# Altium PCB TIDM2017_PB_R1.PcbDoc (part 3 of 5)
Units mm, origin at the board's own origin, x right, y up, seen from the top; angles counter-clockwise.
Board outline 120 x 147.5 mm, 4 copper layers (Top Layer, L2, L3, Bottom Layer), stack 1.413 mm thick; 117 components, 53 nets, 3137 pads, 96 vias.
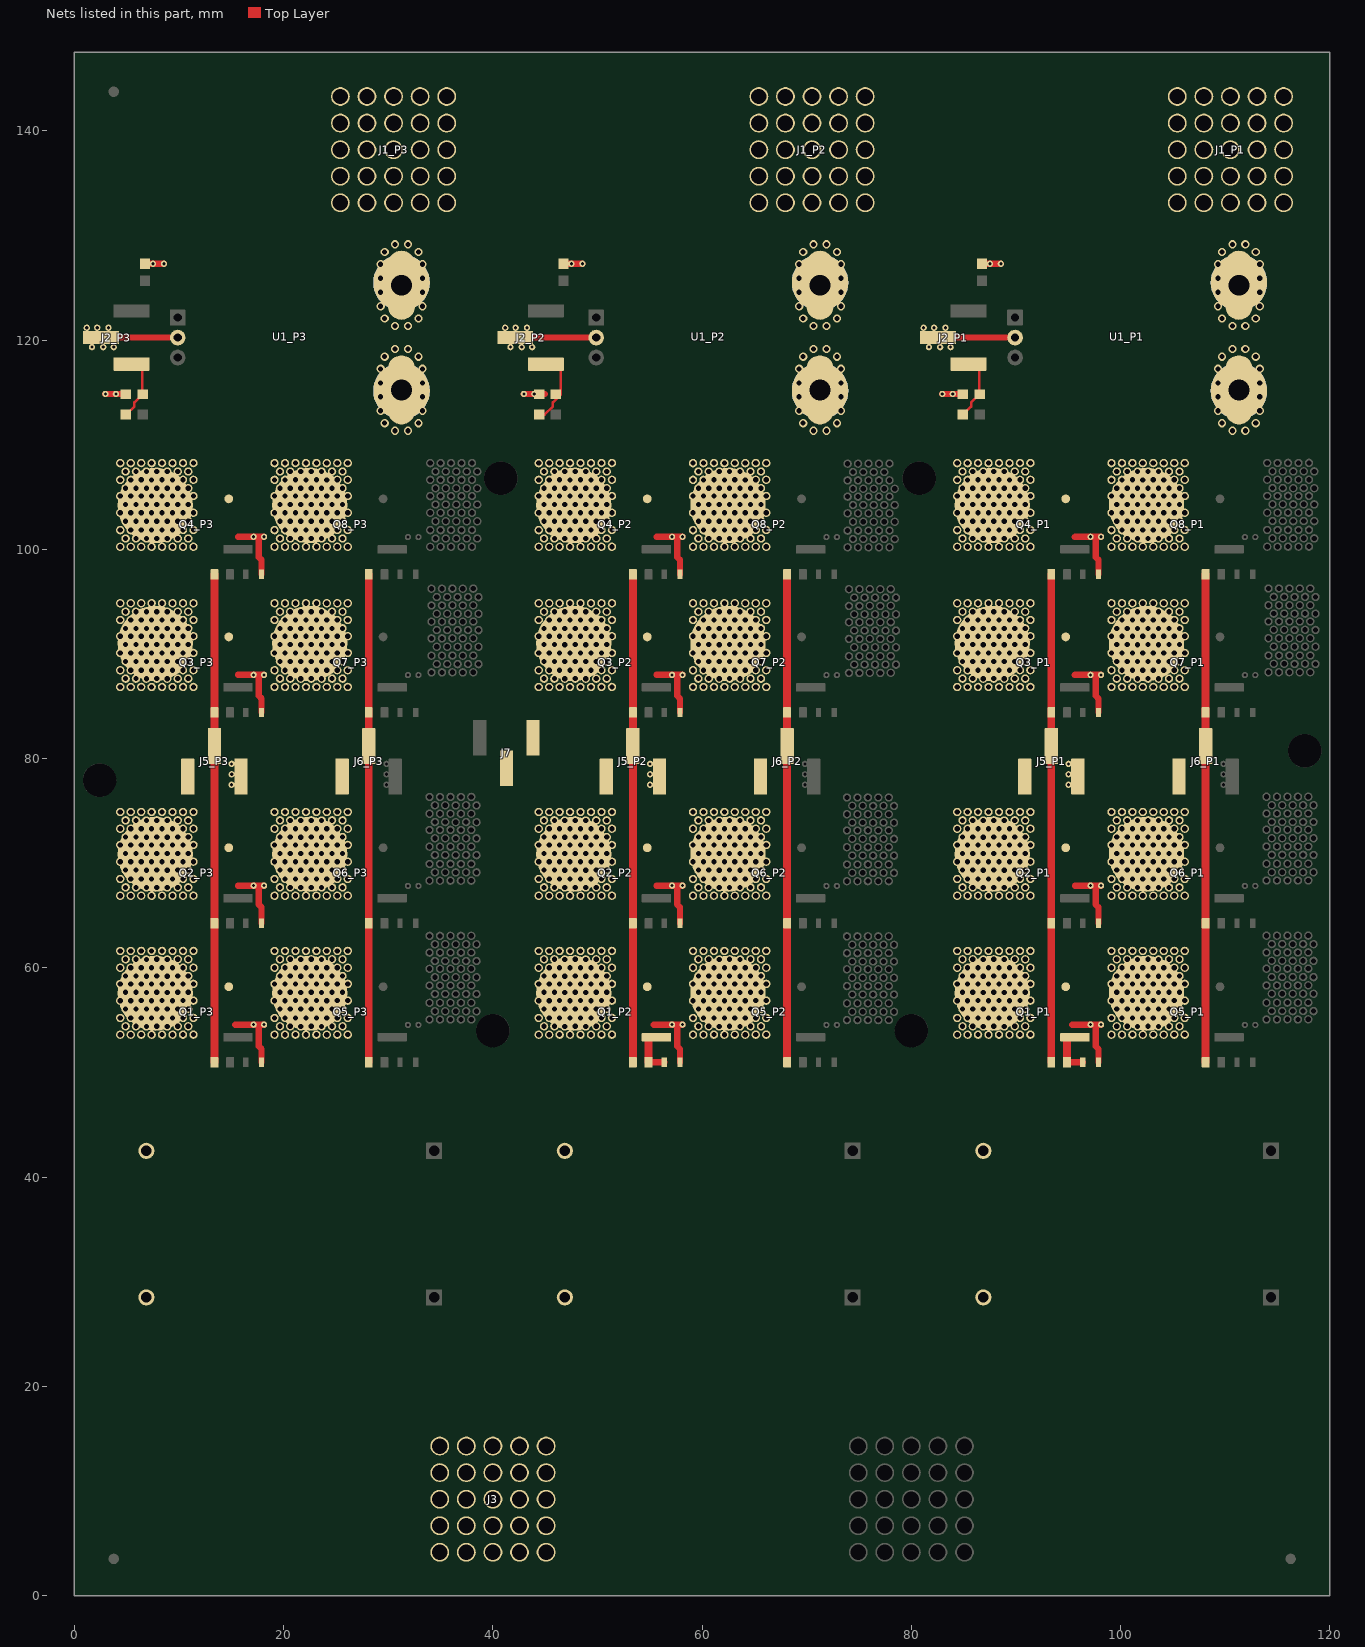
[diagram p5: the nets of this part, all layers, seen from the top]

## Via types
v1: diameter 0.8, hole 0.5, Top Layer to Bottom Layer, 96 vias

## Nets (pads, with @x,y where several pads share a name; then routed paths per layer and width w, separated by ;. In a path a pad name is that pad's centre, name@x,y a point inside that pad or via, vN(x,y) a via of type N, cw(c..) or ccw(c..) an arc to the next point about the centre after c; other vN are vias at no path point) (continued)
D_HS_P1: C1_P1.2 C1_P2.2 C1_P3.2 C2_P1.2 C2_P2.2 C2_P3.2 J3.1 J5_P1.3 J5_P2.3 J5_P3.3 J7.2 J7.3 pad.2@4.376,53.611 pad.2@4.376,55.211 pad.2@4.376,56.861 pad.2@4.376,58.461 pad.2@4.376,60.014 pad.2@4.376,61.614 pad.2@4.376,66.894 pad.2@4.376,68.494 pad.2@4.376,70.144 pad.2@4.376,71.744 pad.2@4.376,73.297 pad.2@4.376,74.897 pad.2@4.376,86.847 pad.2@4.376,88.447 pad.2@4.376,90.097 pad.2@4.376,91.697 pad.2@4.376,93.25 pad.2@4.376,94.85 pad.2@4.376,100.242 pad.2@4.376,101.842 pad.2@4.376,103.492 pad.2@4.376,105.092 pad.2@4.376,106.644 pad.2@4.376,108.244 pad.2@4.889,54.409 pad.2@4.889,56.059 pad.2@4.889,57.659 pad.2@4.889,59.212 pad.2@4.889,60.812 pad.2@4.889,67.693 pad.2@4.889,69.343 pad.2@4.889,70.943 pad.2@4.889,72.496 pad.2@4.889,74.096 pad.2@4.889,87.646 pad.2@4.889,89.296 pad.2@4.889,90.896 pad.2@4.889,92.448 pad.2@4.889,94.048 pad.2@4.889,101.04 pad.2@4.889,102.69 pad.2@4.889,104.29 pad.2@4.889,105.843 pad.2@4.889,107.443 pad.2@5.376,53.611 pad.2@5.376,55.211 pad.2@5.376,56.861 pad.2@5.376,58.461 pad.2@5.376,60.014 pad.2@5.376,61.614 pad.2@5.376,66.894 pad.2@5.376,68.494 pad.2@5.376,70.144 pad.2@5.376,71.744 pad.2@5.376,73.297 pad.2@5.376,74.897 pad.2@5.376,86.847 pad.2@5.376,88.447 pad.2@5.376,90.097 pad.2@5.376,91.697 pad.2@5.376,93.25 pad.2@5.376,94.85 pad.2@5.376,100.242 pad.2@5.376,101.842 pad.2@5.376,103.492 pad.2@5.376,105.092 pad.2@5.376,106.644 pad.2@5.376,108.244 pad.2@5.876,54.409 pad.2@5.876,56.059 pad.2@5.876,57.659 pad.2@5.876,59.212 pad.2@5.876,60.812 pad.2@5.876,67.693 pad.2@5.876,69.343 pad.2@5.876,70.943 pad.2@5.876,72.496 pad.2@5.876,74.096 pad.2@5.876,87.646 pad.2@5.876,89.296 pad.2@5.876,90.896 pad.2@5.876,92.448 pad.2@5.876,94.048 pad.2@5.876,101.04 pad.2@5.876,102.69 pad.2@5.876,104.29 pad.2@5.876,105.843 pad.2@5.876,107.443 pad.2@6.376,53.616 pad.2@6.376,55.216 pad.2@6.376,56.866 pad.2@6.376,58.466 pad.2@6.376,60.019 pad.2@6.376,61.619 pad.2@6.376,66.9 pad.2@6.376,68.5 pad.2@6.376,70.15 pad.2@6.376,71.75 pad.2@6.376,73.303 pad.2@6.376,74.903 pad.2@6.376,86.853 pad.2@6.376,88.453 pad.2@6.376,90.103 pad.2@6.376,91.703 pad.2@6.376,93.256 pad.2@6.376,94.855 pad.2@6.376,100.247 pad.2@6.376,101.847 pad.2@6.376,103.497 pad.2@6.376,105.097 pad.2@6.376,106.65 pad.2@6.376,108.25 pad.2@6.876,54.404 pad.2@6.876,56.054 pad.2@6.876,57.654 pad.2@6.876,59.207 pad.2@6.876,60.807 pad.2@6.876,67.687 pad.2@6.876,69.337 pad.2@6.876,70.937 pad.2@6.876,72.49 pad.2@6.876,74.09 pad.2@6.876,87.64 pad.2@6.876,89.29 pad.2@6.876,90.89 pad.2@6.876,92.443 pad.2@6.876,94.043 pad.2@6.876,101.035 pad.2@6.876,102.685 pad.2@6.876,104.285 pad.2@6.876,105.837 pad.2@6.876,107.437 pad.2@7.376,53.611 pad.2@7.376,55.211 pad.2@7.376,56.861 pad.2@7.376,58.461 pad.2@7.376,60.014 pad.2@7.376,61.614 pad.2@7.376,66.894 pad.2@7.376,68.494 pad.2@7.376,70.144 pad.2@7.376,71.744 pad.2@7.376,73.297 pad.2@7.376,74.897 pad.2@7.376,86.847 pad.2@7.376,88.447 pad.2@7.376,90.097 pad.2@7.376,91.697 pad.2@7.376,93.25 pad.2@7.376,94.85 pad.2@7.376,100.242 pad.2@7.376,101.842 pad.2@7.376,103.492 pad.2@7.376,105.092 pad.2@7.376,106.644 pad.2@7.376,108.244 pad.2@7.876,54.409 pad.2@7.876,56.059 pad.2@7.876,57.659 pad.2@7.876,59.212 pad.2@7.876,60.812 pad.2@7.876,67.693 pad.2@7.876,69.343 pad.2@7.876,70.943 pad.2@7.876,72.496 pad.2@7.876,74.096 pad.2@7.876,87.646 pad.2@7.876,89.296 pad.2@7.876,90.896 pad.2@7.876,92.448 pad.2@7.876,94.048 pad.2@7.876,101.04 pad.2@7.876,102.69 pad.2@7.876,104.29 pad.2@7.876,105.843 pad.2@7.876,107.443 pad.2@8.376,53.616 pad.2@8.376,55.216 pad.2@8.376,56.866 pad.2@8.376,58.466 pad.2@8.376,60.019 pad.2@8.376,61.619 pad.2@8.376,66.9 pad.2@8.376,68.5 pad.2@8.376,70.15 pad.2@8.376,71.75 pad.2@8.376,73.303 pad.2@8.376,74.903 pad.2@8.376,86.853 pad.2@8.376,88.453 pad.2@8.376,90.103 pad.2@8.376,91.703 pad.2@8.376,93.256 pad.2@8.376,94.855 pad.2@8.376,100.247 pad.2@8.376,101.847 pad.2@8.376,103.497 pad.2@8.376,105.097 pad.2@8.376,106.65 pad.2@8.376,108.25 pad.2@8.876,54.404 pad.2@8.876,56.054 pad.2@8.876,57.654 pad.2@8.876,59.207 pad.2@8.876,60.807 pad.2@8.876,67.687 pad.2@8.876,69.337 pad.2@8.876,70.937 pad.2@8.876,72.49 pad.2@8.876,74.09 pad.2@8.876,87.64 pad.2@8.876,89.29 pad.2@8.876,90.89 pad.2@8.876,92.443 pad.2@8.876,94.043 pad.2@8.876,101.035 pad.2@8.876,102.685 pad.2@8.876,104.285 pad.2@8.876,105.837 pad.2@8.876,107.437 pad.2@9.376,53.611 pad.2@9.376,55.211 pad.2@9.376,56.861 pad.2@9.376,58.461 pad.2@9.376,60.014 pad.2@9.376,61.614 pad.2@9.376,66.894 pad.2@9.376,68.494 pad.2@9.376,70.144 pad.2@9.376,71.744 pad.2@9.376,73.297 pad.2@9.376,74.897 pad.2@9.376,86.847 pad.2@9.376,88.447 pad.2@9.376,90.097 pad.2@9.376,91.697 pad.2@9.376,93.25 pad.2@9.376,94.85 pad.2@9.376,100.242 pad.2@9.376,101.842 pad.2@9.376,103.492 pad.2@9.376,105.092 pad.2@9.376,106.644 pad.2@9.376,108.244 pad.2@9.876,54.409 pad.2@9.876,56.059 pad.2@9.876,57.659 pad.2@9.876,59.212 pad.2@9.876,60.812 pad.2@9.876,67.693 pad.2@9.876,69.343 pad.2@9.876,70.943 pad.2@9.876,72.496 pad.2@9.876,74.096 pad.2@9.876,87.646 pad.2@9.876,89.296 pad.2@9.876,90.896 pad.2@9.876,92.448 pad.2@9.876,94.048 pad.2@9.876,101.04 pad.2@9.876,102.69 pad.2@9.876,104.29 pad.2@9.876,105.843 pad.2@9.876,107.443 pad.2@10.376,53.616 pad.2@10.376,55.216 pad.2@10.376,56.866 pad.2@10.376,58.466 pad.2@10.376,60.019 pad.2@10.376,61.619 pad.2@10.376,66.9 pad.2@10.376,68.5 pad.2@10.376,70.15 pad.2@10.376,71.75 pad.2@10.376,73.303 pad.2@10.376,74.903 pad.2@10.376,86.853 pad.2@10.376,88.453 pad.2@10.376,90.103 pad.2@10.376,91.703 pad.2@10.376,93.256 pad.2@10.376,94.855 pad.2@10.376,100.247 pad.2@10.376,101.847 pad.2@10.376,103.497 pad.2@10.376,105.097 pad.2@10.376,106.65 pad.2@10.376,108.25 pad.2@10.876,54.409 pad.2@10.876,56.059 pad.2@10.876,57.659 pad.2@10.876,59.212 pad.2@10.876,60.812 pad.2@10.876,67.693 pad.2@10.876,69.343 pad.2@10.876,70.943 pad.2@10.876,72.496 pad.2@10.876,74.096 pad.2@10.876,87.646 pad.2@10.876,89.296 pad.2@10.876,90.896 pad.2@10.876,92.448 pad.2@10.876,94.048 pad.2@10.876,101.04 pad.2@10.876,102.69 pad.2@10.876,104.29 pad.2@10.876,105.843 pad.2@10.876,107.443 pad.2@11.376,53.616 pad.2@11.376,55.216 pad.2@11.376,56.866 pad.2@11.376,58.466 pad.2@11.376,60.019 pad.2@11.376,61.619 pad.2@11.376,66.9 pad.2@11.376,68.5 pad.2@11.376,70.15 pad.2@11.376,71.75 pad.2@11.376,73.303 pad.2@11.376,74.903 pad.2@11.376,86.853 pad.2@11.376,88.453 pad.2@11.376,90.103 pad.2@11.376,91.703 pad.2@11.376,93.256 pad.2@11.376,94.855 pad.2@11.376,100.247 pad.2@11.376,101.847 pad.2@11.376,103.497 pad.2@11.376,105.097 pad.2@11.376,106.65 pad.2@11.376,108.25 pad.2@44.376,53.611 pad.2@44.376,55.211 pad.2@44.376,56.861 pad.2@44.376,58.461 pad.2@44.376,60.014 pad.2@44.376,61.614 pad.2@44.376,66.894 pad.2@44.376,68.494 pad.2@44.376,70.144 pad.2@44.376,71.744 pad.2@44.376,73.297 pad.2@44.376,74.897 pad.2@44.376,86.847 pad.2@44.376,88.447 pad.2@44.376,90.097 pad.2@44.376,91.697 pad.2@44.376,93.25 pad.2@44.376,94.85 pad.2@44.376,100.242 pad.2@44.376,101.842 pad.2@44.376,103.492 pad.2@44.376,105.092 pad.2@44.376,106.644 pad.2@44.376,108.244 pad.2@44.889,54.409 pad.2@44.889,56.059 pad.2@44.889,57.659 pad.2@44.889,59.212 pad.2@44.889,60.812 pad.2@44.889,67.693 pad.2@44.889,69.343 pad.2@44.889,70.943 pad.2@44.889,72.496 pad.2@44.889,74.096 pad.2@44.889,87.646 pad.2@44.889,89.296 pad.2@44.889,90.896 pad.2@44.889,92.448 pad.2@44.889,94.048 pad.2@44.889,101.04 pad.2@44.889,102.69 pad.2@44.889,104.29 pad.2@44.889,105.843 pad.2@44.889,107.443 pad.2@45.376,53.611 pad.2@45.376,55.211 pad.2@45.376,56.861 pad.2@45.376,58.461 pad.2@45.376,60.014 pad.2@45.376,61.614 pad.2@45.376,66.894 pad.2@45.376,68.494 pad.2@45.376,70.144 pad.2@45.376,71.744 pad.2@45.376,73.297 pad.2@45.376,74.897 pad.2@45.376,86.847 pad.2@45.376,88.447 pad.2@45.376,90.097 pad.2@45.376,91.697 pad.2@45.376,93.25 pad.2@45.376,94.85 pad.2@45.376,100.242 pad.2@45.376,101.842 pad.2@45.376,103.492 pad.2@45.376,105.092 pad.2@45.376,106.644 pad.2@45.376,108.244 pad.2@45.876,54.409 pad.2@45.876,56.059 pad.2@45.876,57.659 pad.2@45.876,59.212 pad.2@45.876,60.812 pad.2@45.876,67.693 pad.2@45.876,69.343 pad.2@45.876,70.943 pad.2@45.876,72.496 pad.2@45.876,74.096 pad.2@45.876,87.646 pad.2@45.876,89.296 pad.2@45.876,90.896 pad.2@45.876,92.448 pad.2@45.876,94.048 pad.2@45.876,101.04 pad.2@45.876,102.69 pad.2@45.876,104.29 pad.2@45.876,105.843 pad.2@45.876,107.443 pad.2@46.376,53.616 pad.2@46.376,55.216 pad.2@46.376,56.866 pad.2@46.376,58.466 pad.2@46.376,60.019 pad.2@46.376,61.619 pad.2@46.376,66.9 pad.2@46.376,68.5 pad.2@46.376,70.15 pad.2@46.376,71.75 pad.2@46.376,73.303 pad.2@46.376,74.903 pad.2@46.376,86.853 pad.2@46.376,88.453 pad.2@46.376,90.103 pad.2@46.376,91.703 pad.2@46.376,93.256 pad.2@46.376,94.855 pad.2@46.376,100.247 pad.2@46.376,101.847 pad.2@46.376,103.497 pad.2@46.376,105.097 pad.2@46.376,106.65 pad.2@46.376,108.25 pad.2@46.876,54.404 pad.2@46.876,56.054 pad.2@46.876,57.654 pad.2@46.876,59.207 pad.2@46.876,60.807 pad.2@46.876,67.687 pad.2@46.876,69.337 pad.2@46.876,70.937 pad.2@46.876,72.49 pad.2@46.876,74.09 pad.2@46.876,87.64 pad.2@46.876,89.29 pad.2@46.876,90.89 pad.2@46.876,92.443 pad.2@46.876,94.043 pad.2@46.876,101.035 pad.2@46.876,102.685 pad.2@46.876,104.285 pad.2@46.876,105.837 pad.2@46.876,107.437 pad.2@47.376,53.611 pad.2@47.376,55.211 pad.2@47.376,56.861 pad.2@47.376,58.461 pad.2@47.376,60.014 pad.2@47.376,61.614 pad.2@47.376,66.894 pad.2@47.376,68.494 pad.2@47.376,70.144 pad.2@47.376,71.744 pad.2@47.376,73.297 pad.2@47.376,74.897 pad.2@47.376,86.847 pad.2@47.376,88.447 pad.2@47.376,90.097 pad.2@47.376,91.697 pad.2@47.376,93.25 pad.2@47.376,94.85 pad.2@47.376,100.242 pad.2@47.376,101.842 pad.2@47.376,103.492 pad.2@47.376,105.092 pad.2@47.376,106.644 pad.2@47.376,108.244 pad.2@47.876,54.409 pad.2@47.876,56.059 pad.2@47.876,57.659 pad.2@47.876,59.212 pad.2@47.876,60.812 pad.2@47.876,67.693 pad.2@47.876,69.343 pad.2@47.876,70.943 pad.2@47.876,72.496 pad.2@47.876,74.096 pad.2@47.876,87.646 pad.2@47.876,89.296 pad.2@47.876,90.896 pad.2@47.876,92.448 pad.2@47.876,94.048 pad.2@47.876,101.04 pad.2@47.876,102.69 pad.2@47.876,104.29 pad.2@47.876,105.843 pad.2@47.876,107.443 pad.2@48.376,53.616 pad.2@48.376,55.216 pad.2@48.376,56.866 pad.2@48.376,58.466 pad.2@48.376,60.019 pad.2@48.376,61.619 pad.2@48.376,66.9 pad.2@48.376,68.5 pad.2@48.376,70.15 pad.2@48.376,71.75 pad.2@48.376,73.303 pad.2@48.376,74.903 pad.2@48.376,86.853 pad.2@48.376,88.453 pad.2@48.376,90.103 pad.2@48.376,91.703 pad.2@48.376,93.256 pad.2@48.376,94.855 pad.2@48.376,100.247 pad.2@48.376,101.847 pad.2@48.376,103.497 pad.2@48.376,105.097 pad.2@48.376,106.65 pad.2@48.376,108.25 pad.2@48.876,54.404 pad.2@48.876,56.054 pad.2@48.876,57.654 pad.2@48.876,59.207 pad.2@48.876,60.807 pad.2@48.876,67.687 pad.2@48.876,69.337 pad.2@48.876,70.937 pad.2@48.876,72.49 pad.2@48.876,74.09 pad.2@48.876,87.64 pad.2@48.876,89.29 pad.2@48.876,90.89 pad.2@48.876,92.443 pad.2@48.876,94.043 pad.2@48.876,101.035 pad.2@48.876,102.685 pad.2@48.876,104.285 pad.2@48.876,105.837 pad.2@48.876,107.437 pad.2@49.376,53.611 pad.2@49.376,55.211 pad.2@49.376,56.861 pad.2@49.376,58.461 pad.2@49.376,60.014 pad.2@49.376,61.614 pad.2@49.376,66.894 pad.2@49.376,68.494 pad.2@49.376,70.144 pad.2@49.376,71.744 pad.2@49.376,73.297 pad.2@49.376,74.897 pad.2@49.376,86.847 pad.2@49.376,88.447 pad.2@49.376,90.097 pad.2@49.376,91.697 pad.2@49.376,93.25 pad.2@49.376,94.85 pad.2@49.376,100.242 pad.2@49.376,101.842 pad.2@49.376,103.492 pad.2@49.376,105.092 pad.2@49.376,106.644 pad.2@49.376,108.244 pad.2@49.876,54.409 pad.2@49.876,56.059 pad.2@49.876,57.659 pad.2@49.876,59.212 pad.2@49.876,60.812 pad.2@49.876,67.693 pad.2@49.876,69.343 pad.2@49.876,70.943 pad.2@49.876,72.496 pad.2@49.876,74.096 pad.2@49.876,87.646 pad.2@49.876,89.296 pad.2@49.876,90.896 pad.2@49.876,92.448 pad.2@49.876,94.048 pad.2@49.876,101.04 pad.2@49.876,102.69 pad.2@49.876,104.29 pad.2@49.876,105.843 pad.2@49.876,107.443 pad.2@50.376,53.616 pad.2@50.376,55.216 pad.2@50.376,56.866 pad.2@50.376,58.466 pad.2@50.376,60.019 pad.2@50.376,61.619 pad.2@50.376,66.9 pad.2@50.376,68.5 pad.2@50.376,70.15 pad.2@50.376,71.75 pad.2@50.376,73.303 pad.2@50.376,74.903 pad.2@50.376,86.853 pad.2@50.376,88.453 pad.2@50.376,90.103 pad.2@50.376,91.703 pad.2@50.376,93.256 pad.2@50.376,94.855 pad.2@50.376,100.247 pad.2@50.376,101.847 pad.2@50.376,103.497 pad.2@50.376,105.097 pad.2@50.376,106.65 pad.2@50.376,108.25 pad.2@50.876,54.409 pad.2@50.876,56.059 pad.2@50.876,57.659 pad.2@50.876,59.212 pad.2@50.876,60.812 pad.2@50.876,67.693 pad.2@50.876,69.343 pad.2@50.876,70.943 pad.2@50.876,72.496 pad.2@50.876,74.096 pad.2@50.876,87.646 pad.2@50.876,89.296 pad.2@50.876,90.896 pad.2@50.876,92.448 pad.2@50.876,94.048 pad.2@50.876,101.04 pad.2@50.876,102.69 pad.2@50.876,104.29 pad.2@50.876,105.843 pad.2@50.876,107.443 pad.2@51.376,53.616 pad.2@51.376,55.216 pad.2@51.376,56.866 pad.2@51.376,58.466 pad.2@51.376,60.019 pad.2@51.376,61.619 pad.2@51.376,66.9 pad.2@51.376,68.5 pad.2@51.376,70.15 pad.2@51.376,71.75 pad.2@51.376,73.303 pad.2@51.376,74.903 pad.2@51.376,86.853 pad.2@51.376,88.453 pad.2@51.376,90.103 pad.2@51.376,91.703 pad.2@51.376,93.256 pad.2@51.376,94.855 pad.2@51.376,100.247 pad.2@51.376,101.847 pad.2@51.376,103.497 pad.2@51.376,105.097 pad.2@51.376,106.65 pad.2@51.376,108.25 pad.2@84.376,53.611 pad.2@84.376,55.211 pad.2@84.376,56.861 pad.2@84.376,58.461 pad.2@84.376,60.014 pad.2@84.376,61.614 pad.2@84.376,66.894 pad.2@84.376,68.494 pad.2@84.376,70.144 pad.2@84.376,71.744 pad.2@84.376,73.297 pad.2@84.376,74.897 pad.2@84.376,86.847 pad.2@84.376,88.447 pad.2@84.376,90.097 pad.2@84.376,91.697 pad.2@84.376,93.25 pad.2@84.376,94.85 pad.2@84.376,100.242 pad.2@84.376,101.842 pad.2@84.376,103.492 pad.2@84.376,105.092 pad.2@84.376,106.644 pad.2@84.376,108.244 pad.2@84.889,54.409 pad.2@84.889,56.059 pad.2@84.889,57.659 pad.2@84.889,59.212 pad.2@84.889,60.812 pad.2@84.889,67.693 pad.2@84.889,69.343 pad.2@84.889,70.943 pad.2@84.889,72.496 pad.2@84.889,74.096 pad.2@84.889,87.646 pad.2@84.889,89.296 pad.2@84.889,90.896 pad.2@84.889,92.448 pad.2@84.889,94.048 pad.2@84.889,101.04 pad.2@84.889,102.69 pad.2@84.889,104.29 pad.2@84.889,105.843 pad.2@84.889,107.443 pad.2@85.376,53.611 pad.2@85.376,55.211 pad.2@85.376,56.861 pad.2@85.376,58.461 pad.2@85.376,60.014 pad.2@85.376,61.614 pad.2@85.376,66.894 pad.2@85.376,68.494 pad.2@85.376,70.144 pad.2@85.376,71.744 pad.2@85.376,73.297 pad.2@85.376,74.897 pad.2@85.376,86.847 pad.2@85.376,88.447 pad.2@85.376,90.097 pad.2@85.376,91.697 pad.2@85.376,93.25 pad.2@85.376,94.85 pad.2@85.376,100.242 pad.2@85.376,101.842 pad.2@85.376,103.492 pad.2@85.376,105.092 pad.2@85.376,106.644 pad.2@85.376,108.244 pad.2@85.876,54.409 pad.2@85.876,56.059 pad.2@85.876,57.659 pad.2@85.876,59.212 pad.2@85.876,60.812 pad.2@85.876,67.693 pad.2@85.876,69.343 pad.2@85.876,70.943 pad.2@85.876,72.496 pad.2@85.876,74.096 pad.2@85.876,87.646 pad.2@85.876,89.296 pad.2@85.876,90.896 pad.2@85.876,92.448 pad.2@85.876,94.048 pad.2@85.876,101.04 pad.2@85.876,102.69 pad.2@85.876,104.29 pad.2@85.876,105.843 pad.2@85.876,107.443 pad.2@86.376,53.616 pad.2@86.376,55.216 pad.2@86.376,56.866 pad.2@86.376,58.466 pad.2@86.376,60.019 pad.2@86.376,61.619 pad.2@86.376,66.9 pad.2@86.376,68.5 pad.2@86.376,70.15 pad.2@86.376,71.75 pad.2@86.376,73.303 pad.2@86.376,74.903 pad.2@86.376,86.853 pad.2@86.376,88.453 pad.2@86.376,90.103 pad.2@86.376,91.703 pad.2@86.376,93.256 pad.2@86.376,94.855 pad.2@86.376,100.247 pad.2@86.376,101.847 pad.2@86.376,103.497 pad.2@86.376,105.097 pad.2@86.376,106.65 pad.2@86.376,108.25 pad.2@86.876,54.404 pad.2@86.876,56.054 pad.2@86.876,57.654 pad.2@86.876,59.207 pad.2@86.876,60.807 pad.2@86.876,67.687 pad.2@86.876,69.337 pad.2@86.876,70.937 pad.2@86.876,72.49 pad.2@86.876,74.09 pad.2@86.876,87.64 pad.2@86.876,89.29 pad.2@86.876,90.89 pad.2@86.876,92.443 pad.2@86.876,94.043 pad.2@86.876,101.035 pad.2@86.876,102.685 pad.2@86.876,104.285 pad.2@86.876,105.837 pad.2@86.876,107.437 pad.2@87.376,53.611 pad.2@87.376,55.211 pad.2@87.376,56.861 pad.2@87.376,58.461 pad.2@87.376,60.014 pad.2@87.376,61.614 pad.2@87.376,66.894 pad.2@87.376,68.494 pad.2@87.376,70.144 pad.2@87.376,71.744 pad.2@87.376,73.297 pad.2@87.376,74.897 pad.2@87.376,86.847 pad.2@87.376,88.447 pad.2@87.376,90.097 pad.2@87.376,91.697 pad.2@87.376,93.25 pad.2@87.376,94.85 pad.2@87.376,100.242 pad.2@87.376,101.842 pad.2@87.376,103.492 pad.2@87.376,105.092 pad.2@87.376,106.644 pad.2@87.376,108.244 pad.2@87.876,54.409 pad.2@87.876,56.059 pad.2@87.876,57.659 pad.2@87.876,59.212 pad.2@87.876,60.812 pad.2@87.876,67.693 pad.2@87.876,69.343 pad.2@87.876,70.943 pad.2@87.876,72.496 pad.2@87.876,74.096 pad.2@87.876,87.646 pad.2@87.876,89.296 pad.2@87.876,90.896 pad.2@87.876,92.448 pad.2@87.876,94.048 pad.2@87.876,101.04 pad.2@87.876,102.69 pad.2@87.876,104.29 pad.2@87.876,105.843 pad.2@87.876,107.443 pad.2@88.376,53.616 pad.2@88.376,55.216 pad.2@88.376,56.866 pad.2@88.376,58.466 pad.2@88.376,60.019 pad.2@88.376,61.619 pad.2@88.376,66.9 pad.2@88.376,68.5 pad.2@88.376,70.15 pad.2@88.376,71.75 pad.2@88.376,73.303 pad.2@88.376,74.903 pad.2@88.376,86.853 pad.2@88.376,88.453 pad.2@88.376,90.103 pad.2@88.376,91.703 pad.2@88.376,93.256 pad.2@88.376,94.855 pad.2@88.376,100.247 pad.2@88.376,101.847 pad.2@88.376,103.497 pad.2@88.376,105.097 pad.2@88.376,106.65 pad.2@88.376,108.25 pad.2@88.876,54.404 pad.2@88.876,56.054 pad.2@88.876,57.654 pad.2@88.876,59.207 pad.2@88.876,60.807 pad.2@88.876,67.687 pad.2@88.876,69.337 pad.2@88.876,70.937 pad.2@88.876,72.49 pad.2@88.876,74.09 pad.2@88.876,87.64 pad.2@88.876,89.29 pad.2@88.876,90.89 pad.2@88.876,92.443 pad.2@88.876,94.043 pad.2@88.876,101.035 pad.2@88.876,102.685 pad.2@88.876,104.285 pad.2@88.876,105.837 pad.2@88.876,107.437 pad.2@89.376,53.611 pad.2@89.376,55.211 pad.2@89.376,56.861 pad.2@89.376,58.461 pad.2@89.376,60.014 pad.2@89.376,61.614 pad.2@89.376,66.894 pad.2@89.376,68.494 pad.2@89.376,70.144 pad.2@89.376,71.744 pad.2@89.376,73.297 pad.2@89.376,74.897 pad.2@89.376,86.847 pad.2@89.376,88.447 pad.2@89.376,90.097 pad.2@89.376,91.697 pad.2@89.376,93.25 pad.2@89.376,94.85 pad.2@89.376,100.242 pad.2@89.376,101.842 pad.2@89.376,103.492 pad.2@89.376,105.092 pad.2@89.376,106.644 pad.2@89.376,108.244 pad.2@89.876,54.409 pad.2@89.876,56.059 pad.2@89.876,57.659 pad.2@89.876,59.212 pad.2@89.876,60.812 pad.2@89.876,67.693 pad.2@89.876,69.343 pad.2@89.876,70.943 pad.2@89.876,72.496 pad.2@89.876,74.096 pad.2@89.876,87.646 pad.2@89.876,89.296 pad.2@89.876,90.896 pad.2@89.876,92.448 pad.2@89.876,94.048 pad.2@89.876,101.04 pad.2@89.876,102.69 pad.2@89.876,104.29 pad.2@89.876,105.843 pad.2@89.876,107.443 pad.2@90.376,53.616 pad.2@90.376,55.216 pad.2@90.376,56.866 pad.2@90.376,58.466 pad.2@90.376,60.019 pad.2@90.376,61.619 pad.2@90.376,66.9 pad.2@90.376,68.5 pad.2@90.376,70.15 pad.2@90.376,71.75 pad.2@90.376,73.303 pad.2@90.376,74.903 pad.2@90.376,86.853 pad.2@90.376,88.453 pad.2@90.376,90.103 pad.2@90.376,91.703 pad.2@90.376,93.256 pad.2@90.376,94.855 pad.2@90.376,100.247 pad.2@90.376,101.847 pad.2@90.376,103.497 pad.2@90.376,105.097 pad.2@90.376,106.65 pad.2@90.376,108.25 pad.2@90.876,54.409 pad.2@90.876,56.059 pad.2@90.876,57.659 pad.2@90.876,59.212 pad.2@90.876,60.812 pad.2@90.876,67.693 pad.2@90.876,69.343 pad.2@90.876,70.943 pad.2@90.876,72.496 pad.2@90.876,74.096 pad.2@90.876,87.646 pad.2@90.876,89.296 pad.2@90.876,90.896 pad.2@90.876,92.448 pad.2@90.876,94.048 pad.2@90.876,101.04 pad.2@90.876,102.69 pad.2@90.876,104.29 pad.2@90.876,105.843 pad.2@90.876,107.443 pad.2@91.376,53.616 pad.2@91.376,55.216 pad.2@91.376,56.866 pad.2@91.376,58.466 pad.2@91.376,60.019 pad.2@91.376,61.619 pad.2@91.376,66.9 pad.2@91.376,68.5 pad.2@91.376,70.15 pad.2@91.376,71.75 pad.2@91.376,73.303 pad.2@91.376,74.903 pad.2@91.376,86.853 pad.2@91.376,88.453 pad.2@91.376,90.103 pad.2@91.376,91.703 pad.2@91.376,93.256 pad.2@91.376,94.855 pad.2@91.376,100.247 pad.2@91.376,101.847 pad.2@91.376,103.497 pad.2@91.376,105.097 pad.2@91.376,106.65 pad.2@91.376,108.25 Q1_P1.9 Q1_P2.9 Q1_P3.9 Q2_P1.9 Q2_P2.9 Q2_P3.9 Q3_P1.9 Q3_P2.9 Q3_P3.9 Q4_P1.9 Q4_P2.9 Q4_P3.9
D_LS_P1: J5_P1.1 J6_P1.3 pad.2@95.026,77.5 pad.2@95.026,79.5 pad.2@95.029,78.5 pad.2@97.126,54.572 pad.2@97.126,67.855 pad.2@97.126,88.008 pad.2@97.126,101.203 pad.2@98.126,54.572 pad.2@98.126,67.855 pad.2@98.126,88.008 pad.2@98.126,101.203 pad.2@99.126,53.611 pad.2@99.126,55.211 pad.2@99.126,56.861 pad.2@99.126,58.461 pad.2@99.126,60.014 pad.2@99.126,61.614 pad.2@99.126,66.894 pad.2@99.126,68.494 pad.2@99.126,70.144 pad.2@99.126,71.744 pad.2@99.126,73.297 pad.2@99.126,74.897 pad.2@99.126,86.847 pad.2@99.126,88.447 pad.2@99.126,90.097 pad.2@99.126,91.697 pad.2@99.126,93.25 pad.2@99.126,94.85 pad.2@99.126,100.242 pad.2@99.126,101.842 pad.2@99.126,103.492 pad.2@99.126,105.092 pad.2@99.126,106.644 pad.2@99.126,108.244 pad.2@99.639,54.409 pad.2@99.639,56.059 pad.2@99.639,57.659 pad.2@99.639,59.212 pad.2@99.639,60.812 pad.2@99.639,67.693 pad.2@99.639,69.343 pad.2@99.639,70.943 pad.2@99.639,72.496 pad.2@99.639,74.096 pad.2@99.639,87.646 pad.2@99.639,89.296 pad.2@99.639,90.896 pad.2@99.639,92.448 pad.2@99.639,94.048 pad.2@99.639,101.04 pad.2@99.639,102.69 pad.2@99.639,104.29 pad.2@99.639,105.843 pad.2@99.639,107.443 pad.2@100.126,53.611 pad.2@100.126,55.211 pad.2@100.126,56.861 pad.2@100.126,58.461 pad.2@100.126,60.014 pad.2@100.126,61.614 pad.2@100.126,66.894 pad.2@100.126,68.494 pad.2@100.126,70.144 pad.2@100.126,71.744 pad.2@100.126,73.297 pad.2@100.126,74.897 pad.2@100.126,86.847 pad.2@100.126,88.447 pad.2@100.126,90.097 pad.2@100.126,91.697 pad.2@100.126,93.25 pad.2@100.126,94.85 pad.2@100.126,100.242 pad.2@100.126,101.842 pad.2@100.126,103.492 pad.2@100.126,105.092 pad.2@100.126,106.644 pad.2@100.126,108.244 pad.2@100.626,54.409 pad.2@100.626,56.059 pad.2@100.626,57.659 pad.2@100.626,59.212 pad.2@100.626,60.812 pad.2@100.626,67.693 pad.2@100.626,69.343 pad.2@100.626,70.943 pad.2@100.626,72.496 pad.2@100.626,74.096 pad.2@100.626,87.646 pad.2@100.626,89.296 pad.2@100.626,90.896 pad.2@100.626,92.448 pad.2@100.626,94.048 pad.2@100.626,101.04 pad.2@100.626,102.69 pad.2@100.626,104.29 pad.2@100.626,105.843 pad.2@100.626,107.443 pad.2@101.126,53.616 pad.2@101.126,55.216 pad.2@101.126,56.866 pad.2@101.126,58.466 pad.2@101.126,60.019 pad.2@101.126,61.619 pad.2@101.126,66.9 pad.2@101.126,68.5 pad.2@101.126,70.15 pad.2@101.126,71.75 pad.2@101.126,73.303 pad.2@101.126,74.903 pad.2@101.126,86.853 pad.2@101.126,88.453 pad.2@101.126,90.103 pad.2@101.126,91.703 pad.2@101.126,93.256 pad.2@101.126,94.855 pad.2@101.126,100.247 pad.2@101.126,101.847 pad.2@101.126,103.497 pad.2@101.126,105.097 pad.2@101.126,106.65 pad.2@101.126,108.25 pad.2@101.626,54.404 pad.2@101.626,56.054 pad.2@101.626,57.654 pad.2@101.626,59.207 pad.2@101.626,60.807 pad.2@101.626,67.687 pad.2@101.626,69.337 pad.2@101.626,70.937 pad.2@101.626,72.49 pad.2@101.626,74.09 pad.2@101.626,87.64 pad.2@101.626,89.29 pad.2@101.626,90.89 pad.2@101.626,92.443 pad.2@101.626,94.043 pad.2@101.626,101.035 pad.2@101.626,102.685 pad.2@101.626,104.285 pad.2@101.626,105.837 pad.2@101.626,107.437 pad.2@102.126,53.611 pad.2@102.126,55.211 pad.2@102.126,56.861 pad.2@102.126,58.461 pad.2@102.126,60.014 pad.2@102.126,61.614 pad.2@102.126,66.894 pad.2@102.126,68.494 pad.2@102.126,70.144 pad.2@102.126,71.744 pad.2@102.126,73.297 pad.2@102.126,74.897 pad.2@102.126,86.847 pad.2@102.126,88.447 pad.2@102.126,90.097 pad.2@102.126,91.697 pad.2@102.126,93.25 pad.2@102.126,94.85 pad.2@102.126,100.242 pad.2@102.126,101.842 pad.2@102.126,103.492 pad.2@102.126,105.092 pad.2@102.126,106.644 pad.2@102.126,108.244 pad.2@102.626,54.409 pad.2@102.626,56.059 pad.2@102.626,57.659 pad.2@102.626,59.212 pad.2@102.626,60.812 pad.2@102.626,67.693 pad.2@102.626,69.343 pad.2@102.626,70.943 pad.2@102.626,72.496 pad.2@102.626,74.096 pad.2@102.626,87.646 pad.2@102.626,89.296 pad.2@102.626,90.896 pad.2@102.626,92.448 pad.2@102.626,94.048 pad.2@102.626,101.04 pad.2@102.626,102.69 pad.2@102.626,104.29 pad.2@102.626,105.843 pad.2@102.626,107.443 pad.2@103.126,53.616 pad.2@103.126,55.216 pad.2@103.126,56.866 pad.2@103.126,58.466 pad.2@103.126,60.019 pad.2@103.126,61.619 pad.2@103.126,66.9 pad.2@103.126,68.5 pad.2@103.126,70.15 pad.2@103.126,71.75 pad.2@103.126,73.303 pad.2@103.126,74.903 pad.2@103.126,86.853 pad.2@103.126,88.453 pad.2@103.126,90.103 pad.2@103.126,91.703 pad.2@103.126,93.256 pad.2@103.126,94.855 pad.2@103.126,100.247 pad.2@103.126,101.847 pad.2@103.126,103.497 pad.2@103.126,105.097 pad.2@103.126,106.65 pad.2@103.126,108.25 pad.2@103.626,54.404 pad.2@103.626,56.054 pad.2@103.626,57.654 pad.2@103.626,59.207 pad.2@103.626,60.807 pad.2@103.626,67.687 pad.2@103.626,69.337 pad.2@103.626,70.937 pad.2@103.626,72.49 pad.2@103.626,74.09 pad.2@103.626,87.64 pad.2@103.626,89.29 pad.2@103.626,90.89 pad.2@103.626,92.443 pad.2@103.626,94.043 pad.2@103.626,101.035 pad.2@103.626,102.685 pad.2@103.626,104.285 pad.2@103.626,105.837 pad.2@103.626,107.437 pad.2@104.126,53.611 pad.2@104.126,55.211 pad.2@104.126,56.861 pad.2@104.126,58.461 pad.2@104.126,60.014 pad.2@104.126,61.614 pad.2@104.126,66.894 pad.2@104.126,68.494 pad.2@104.126,70.144 pad.2@104.126,71.744 pad.2@104.126,73.297 pad.2@104.126,74.897 pad.2@104.126,86.847 pad.2@104.126,88.447 pad.2@104.126,90.097 pad.2@104.126,91.697 pad.2@104.126,93.25 pad.2@104.126,94.85 pad.2@104.126,100.242 pad.2@104.126,101.842 pad.2@104.126,103.492 pad.2@104.126,105.092 pad.2@104.126,106.644 pad.2@104.126,108.244 pad.2@104.626,54.409 pad.2@104.626,56.059 pad.2@104.626,57.659 pad.2@104.626,59.212 pad.2@104.626,60.812 pad.2@104.626,67.693 pad.2@104.626,69.343 pad.2@104.626,70.943 pad.2@104.626,72.496 pad.2@104.626,74.096 pad.2@104.626,87.646 pad.2@104.626,89.296 pad.2@104.626,90.896 pad.2@104.626,92.448 pad.2@104.626,94.048 pad.2@104.626,101.04 pad.2@104.626,102.69 pad.2@104.626,104.29 pad.2@104.626,105.843 pad.2@104.626,107.443 pad.2@105.126,53.616 pad.2@105.126,55.216 pad.2@105.126,56.866 pad.2@105.126,58.466 pad.2@105.126,60.019 pad.2@105.126,61.619 pad.2@105.126,66.9 pad.2@105.126,68.5 pad.2@105.126,70.15 pad.2@105.126,71.75 pad.2@105.126,73.303 pad.2@105.126,74.903 pad.2@105.126,86.853 pad.2@105.126,88.453 pad.2@105.126,90.103 pad.2@105.126,91.703 pad.2@105.126,93.256 pad.2@105.126,94.855 pad.2@105.126,100.247 pad.2@105.126,101.847 pad.2@105.126,103.497 pad.2@105.126,105.097 pad.2@105.126,106.65 pad.2@105.126,108.25 pad.2@105.626,54.409 pad.2@105.626,56.059 pad.2@105.626,57.659 pad.2@105.626,59.212 pad.2@105.626,60.812 pad.2@105.626,67.693 pad.2@105.626,69.343 pad.2@105.626,70.943 pad.2@105.626,72.496 pad.2@105.626,74.096 pad.2@105.626,87.646 pad.2@105.626,89.296 pad.2@105.626,90.896 pad.2@105.626,92.448 pad.2@105.626,94.048 pad.2@105.626,101.04 pad.2@105.626,102.69 pad.2@105.626,104.29 pad.2@105.626,105.843 pad.2@105.626,107.443 pad.2@106.126,53.616 pad.2@106.126,55.216 pad.2@106.126,56.866 pad.2@106.126,58.466 pad.2@106.126,60.019 pad.2@106.126,61.619 pad.2@106.126,66.9 pad.2@106.126,68.5 pad.2@106.126,70.15 pad.2@106.126,71.75 pad.2@106.126,73.303 pad.2@106.126,74.903 pad.2@106.126,86.853 pad.2@106.126,88.453 pad.2@106.126,90.103 pad.2@106.126,91.703 pad.2@106.126,93.256 pad.2@106.126,94.855 pad.2@106.126,100.247 pad.2@106.126,101.847 pad.2@106.126,103.497 pad.2@106.126,105.097 pad.2@106.126,106.65 pad.2@106.126,108.25 Q1_P1.2-3-4-5-6-7-8 Q2_P1.2-3-4-5-6-7-8 Q3_P1.2-3-4-5-6-7-8 Q4_P1.2-3-4-5-6-7-8 Q5_P1.9 Q6_P1.9 Q7_P1.9 Q8_P1.9 R5_P1.1 R6_P1.1 R7_P1.1 R8_P1.1 U1_P1.4 | length 25.1
  Top Layer w0.6: 95.376,54.572 pad.2@97.126,54.572 97.626,54.572 ; 95.626,88 95.634,88.008 pad.2@97.126,88.008 97.626,88.008 ; 95.626,101.178 95.651,101.203 pad.2@97.126,101.203 97.626,101.203 ; 95.634,67.855 pad.2@97.126,67.855 97.626,67.855 ; R5_P1.1@97.876,50.975 97.876,52.25 97.626,52.5 97.626,54.572 ; R6_P1.1@97.876,64.258 97.876,65.805 97.626,66.055 97.626,67.855 ; R7_P1.1@97.876,84.411 97.876,85.75 97.626,86 97.626,88.008 ; R8_P1.1@97.876,97.606 97.876,99 97.626,99.25 97.626,101.203 ; pad.2@98.126,54.572 97.626,54.572 ; pad.2@98.126,67.855 97.626,67.855 ; pad.2@98.126,88.008 97.626,88.008 ; pad.2@98.126,101.203 97.626,101.203
  other v1: 110.691,111.348 111.928,111.348 109.692,112.074 112.927,112.074 109.309,113.25 113.309,113.25 109.309,114.583 113.309,114.583 109.309,115.917 113.309,115.917 109.309,117.25 113.309,117.25 109.692,118.426 112.927,118.426 110.691,119.152 111.928,119.152
D_LS_P2: J5_P2.1 J6_P2.3 pad.2@55.026,77.5 pad.2@55.026,79.5 pad.2@55.029,78.5 pad.2@57.126,54.572 pad.2@57.126,67.855 pad.2@57.126,88.008 pad.2@57.126,101.203 pad.2@58.126,54.572 pad.2@58.126,67.855 pad.2@58.126,88.008 pad.2@58.126,101.203 pad.2@59.126,53.611 pad.2@59.126,55.211 pad.2@59.126,56.861 pad.2@59.126,58.461 pad.2@59.126,60.014 pad.2@59.126,61.614 pad.2@59.126,66.894 pad.2@59.126,68.494 pad.2@59.126,70.144 pad.2@59.126,71.744 pad.2@59.126,73.297 pad.2@59.126,74.897 pad.2@59.126,86.847 pad.2@59.126,88.447 pad.2@59.126,90.097 pad.2@59.126,91.697 pad.2@59.126,93.25 pad.2@59.126,94.85 pad.2@59.126,100.242 pad.2@59.126,101.842 pad.2@59.126,103.492 pad.2@59.126,105.092 pad.2@59.126,106.644 pad.2@59.126,108.244 pad.2@59.639,54.409 pad.2@59.639,56.059 pad.2@59.639,57.659 pad.2@59.639,59.212 pad.2@59.639,60.812 pad.2@59.639,67.693 pad.2@59.639,69.343 pad.2@59.639,70.943 pad.2@59.639,72.496 pad.2@59.639,74.096 pad.2@59.639,87.646 pad.2@59.639,89.296 pad.2@59.639,90.896 pad.2@59.639,92.448 pad.2@59.639,94.048 pad.2@59.639,101.04 pad.2@59.639,102.69 pad.2@59.639,104.29 pad.2@59.639,105.843 pad.2@59.639,107.443 pad.2@60.126,53.611 pad.2@60.126,55.211 pad.2@60.126,56.861 pad.2@60.126,58.461 pad.2@60.126,60.014 pad.2@60.126,61.614 pad.2@60.126,66.894 pad.2@60.126,68.494 pad.2@60.126,70.144 pad.2@60.126,71.744 pad.2@60.126,73.297 pad.2@60.126,74.897 pad.2@60.126,86.847 pad.2@60.126,88.447 pad.2@60.126,90.097 pad.2@60.126,91.697 pad.2@60.126,93.25 pad.2@60.126,94.85 pad.2@60.126,100.242 pad.2@60.126,101.842 pad.2@60.126,103.492 pad.2@60.126,105.092 pad.2@60.126,106.644 pad.2@60.126,108.244 pad.2@60.626,54.409 pad.2@60.626,56.059 pad.2@60.626,57.659 pad.2@60.626,59.212 pad.2@60.626,60.812 pad.2@60.626,67.693 pad.2@60.626,69.343 pad.2@60.626,70.943 pad.2@60.626,72.496 pad.2@60.626,74.096 pad.2@60.626,87.646 pad.2@60.626,89.296 pad.2@60.626,90.896 pad.2@60.626,92.448 pad.2@60.626,94.048 pad.2@60.626,101.04 pad.2@60.626,102.69 pad.2@60.626,104.29 pad.2@60.626,105.843 pad.2@60.626,107.443 pad.2@61.126,53.616 pad.2@61.126,55.216 pad.2@61.126,56.866 pad.2@61.126,58.466 pad.2@61.126,60.019 pad.2@61.126,61.619 pad.2@61.126,66.9 pad.2@61.126,68.5 pad.2@61.126,70.15 pad.2@61.126,71.75 pad.2@61.126,73.303 pad.2@61.126,74.903 pad.2@61.126,86.853 pad.2@61.126,88.453 pad.2@61.126,90.103 pad.2@61.126,91.703 pad.2@61.126,93.256 pad.2@61.126,94.855 pad.2@61.126,100.247 pad.2@61.126,101.847 pad.2@61.126,103.497 pad.2@61.126,105.097 pad.2@61.126,106.65 pad.2@61.126,108.25 pad.2@61.626,54.404 pad.2@61.626,56.054 pad.2@61.626,57.654 pad.2@61.626,59.207 pad.2@61.626,60.807 pad.2@61.626,67.687 pad.2@61.626,69.337 pad.2@61.626,70.937 pad.2@61.626,72.49 pad.2@61.626,74.09 pad.2@61.626,87.64 pad.2@61.626,89.29 pad.2@61.626,90.89 pad.2@61.626,92.443 pad.2@61.626,94.043 pad.2@61.626,101.035 pad.2@61.626,102.685 pad.2@61.626,104.285 pad.2@61.626,105.837 pad.2@61.626,107.437 pad.2@62.126,53.611 pad.2@62.126,55.211 pad.2@62.126,56.861 pad.2@62.126,58.461 pad.2@62.126,60.014 pad.2@62.126,61.614 pad.2@62.126,66.894 pad.2@62.126,68.494 pad.2@62.126,70.144 pad.2@62.126,71.744 pad.2@62.126,73.297 pad.2@62.126,74.897 pad.2@62.126,86.847 pad.2@62.126,88.447 pad.2@62.126,90.097 pad.2@62.126,91.697 pad.2@62.126,93.25 pad.2@62.126,94.85 pad.2@62.126,100.242 pad.2@62.126,101.842 pad.2@62.126,103.492 pad.2@62.126,105.092 pad.2@62.126,106.644 pad.2@62.126,108.244 pad.2@62.626,54.409 pad.2@62.626,56.059 pad.2@62.626,57.659 pad.2@62.626,59.212 pad.2@62.626,60.812 pad.2@62.626,67.693 pad.2@62.626,69.343 pad.2@62.626,70.943 pad.2@62.626,72.496 pad.2@62.626,74.096 pad.2@62.626,87.646 pad.2@62.626,89.296 pad.2@62.626,90.896 pad.2@62.626,92.448 pad.2@62.626,94.048 pad.2@62.626,101.04 pad.2@62.626,102.69 pad.2@62.626,104.29 pad.2@62.626,105.843 pad.2@62.626,107.443 pad.2@63.126,53.616 pad.2@63.126,55.216 pad.2@63.126,56.866 pad.2@63.126,58.466 pad.2@63.126,60.019 pad.2@63.126,61.619 pad.2@63.126,66.9 pad.2@63.126,68.5 pad.2@63.126,70.15 pad.2@63.126,71.75 pad.2@63.126,73.303 pad.2@63.126,74.903 pad.2@63.126,86.853 pad.2@63.126,88.453 pad.2@63.126,90.103 pad.2@63.126,91.703 pad.2@63.126,93.256 pad.2@63.126,94.855 pad.2@63.126,100.247 pad.2@63.126,101.847 pad.2@63.126,103.497 pad.2@63.126,105.097 pad.2@63.126,106.65 pad.2@63.126,108.25 pad.2@63.626,54.404 pad.2@63.626,56.054 pad.2@63.626,57.654 pad.2@63.626,59.207 pad.2@63.626,60.807 pad.2@63.626,67.687 pad.2@63.626,69.337 pad.2@63.626,70.937 pad.2@63.626,72.49 pad.2@63.626,74.09 pad.2@63.626,87.64 pad.2@63.626,89.29 pad.2@63.626,90.89 pad.2@63.626,92.443 pad.2@63.626,94.043 pad.2@63.626,101.035 pad.2@63.626,102.685 pad.2@63.626,104.285 pad.2@63.626,105.837 pad.2@63.626,107.437 pad.2@64.126,53.611 pad.2@64.126,55.211 pad.2@64.126,56.861 pad.2@64.126,58.461 pad.2@64.126,60.014 pad.2@64.126,61.614 pad.2@64.126,66.894 pad.2@64.126,68.494 pad.2@64.126,70.144 pad.2@64.126,71.744 pad.2@64.126,73.297 pad.2@64.126,74.897 pad.2@64.126,86.847 pad.2@64.126,88.447 pad.2@64.126,90.097 pad.2@64.126,91.697 pad.2@64.126,93.25 pad.2@64.126,94.85 pad.2@64.126,100.242 pad.2@64.126,101.842 pad.2@64.126,103.492 pad.2@64.126,105.092 pad.2@64.126,106.644 pad.2@64.126,108.244 pad.2@64.626,54.409 pad.2@64.626,56.059 pad.2@64.626,57.659 pad.2@64.626,59.212 pad.2@64.626,60.812 pad.2@64.626,67.693 pad.2@64.626,69.343 pad.2@64.626,70.943 pad.2@64.626,72.496 pad.2@64.626,74.096 pad.2@64.626,87.646 pad.2@64.626,89.296 pad.2@64.626,90.896 pad.2@64.626,92.448 pad.2@64.626,94.048 pad.2@64.626,101.04 pad.2@64.626,102.69 pad.2@64.626,104.29 pad.2@64.626,105.843 pad.2@64.626,107.443 pad.2@65.126,53.616 pad.2@65.126,55.216 pad.2@65.126,56.866 pad.2@65.126,58.466 pad.2@65.126,60.019 pad.2@65.126,61.619 pad.2@65.126,66.9 pad.2@65.126,68.5 pad.2@65.126,70.15 pad.2@65.126,71.75 pad.2@65.126,73.303 pad.2@65.126,74.903 pad.2@65.126,86.853 pad.2@65.126,88.453 pad.2@65.126,90.103 pad.2@65.126,91.703 pad.2@65.126,93.256 pad.2@65.126,94.855 pad.2@65.126,100.247 pad.2@65.126,101.847 pad.2@65.126,103.497 pad.2@65.126,105.097 pad.2@65.126,106.65 pad.2@65.126,108.25 pad.2@65.626,54.409 pad.2@65.626,56.059 pad.2@65.626,57.659 pad.2@65.626,59.212 pad.2@65.626,60.812 pad.2@65.626,67.693 pad.2@65.626,69.343 pad.2@65.626,70.943 pad.2@65.626,72.496 pad.2@65.626,74.096 pad.2@65.626,87.646 pad.2@65.626,89.296 pad.2@65.626,90.896 pad.2@65.626,92.448 pad.2@65.626,94.048 pad.2@65.626,101.04 pad.2@65.626,102.69 pad.2@65.626,104.29 pad.2@65.626,105.843 pad.2@65.626,107.443 pad.2@66.126,53.616 pad.2@66.126,55.216 pad.2@66.126,56.866 pad.2@66.126,58.466 pad.2@66.126,60.019 pad.2@66.126,61.619 pad.2@66.126,66.9 pad.2@66.126,68.5 pad.2@66.126,70.15 pad.2@66.126,71.75 pad.2@66.126,73.303 pad.2@66.126,74.903 pad.2@66.126,86.853 pad.2@66.126,88.453 pad.2@66.126,90.103 pad.2@66.126,91.703 pad.2@66.126,93.256 pad.2@66.126,94.855 pad.2@66.126,100.247 pad.2@66.126,101.847 pad.2@66.126,103.497 pad.2@66.126,105.097 pad.2@66.126,106.65 pad.2@66.126,108.25 Q1_P2.2-3-4-5-6-7-8 Q2_P2.2-3-4-5-6-7-8 Q3_P2.2-3-4-5-6-7-8 Q4_P2.2-3-4-5-6-7-8 Q5_P2.9 Q6_P2.9 Q7_P2.9 Q8_P2.9 R5_P2.1 R6_P2.1 R7_P2.1 R8_P2.1 U1_P2.4 | length 25.1
  Top Layer w0.6: 55.376,54.572 pad.2@57.126,54.572 57.626,54.572 ; 55.626,88 55.634,88.008 pad.2@57.126,88.008 57.626,88.008 ; 55.626,101.178 55.651,101.203 pad.2@57.126,101.203 57.626,101.203 ; 55.634,67.855 pad.2@57.126,67.855 57.626,67.855 ; R5_P2.1@57.876,50.975 57.876,52.25 57.626,52.5 57.626,54.572 ; R6_P2.1@57.876,64.258 57.876,65.805 57.626,66.055 57.626,67.855 ; R7_P2.1@57.876,84.411 57.876,85.75 57.626,86 57.626,88.008 ; R8_P2.1@57.876,97.606 57.876,99 57.626,99.25 57.626,101.203 ; pad.2@58.126,54.572 57.626,54.572 ; pad.2@58.126,67.855 57.626,67.855 ; pad.2@58.126,88.008 57.626,88.008 ; pad.2@58.126,101.203 57.626,101.203
  other v1: 70.649,111.348 71.885,111.348 69.649,112.074 72.885,112.074 69.267,113.25 73.267,113.25 69.267,114.583 73.267,114.583 69.267,115.917 73.267,115.917 69.267,117.25 73.267,117.25 69.649,118.426 72.885,118.426 70.649,119.152 71.885,119.152
D_LS_P3: J5_P3.1 J6_P3.3 pad.2@15.026,77.5 pad.2@15.026,79.5 pad.2@15.029,78.5 pad.2@17.126,54.572 pad.2@17.126,67.855 pad.2@17.126,88.008 pad.2@17.126,101.203 pad.2@18.126,54.572 pad.2@18.126,67.855 pad.2@18.126,88.008 pad.2@18.126,101.203 pad.2@19.126,53.611 pad.2@19.126,55.211 pad.2@19.126,56.861 pad.2@19.126,58.461 pad.2@19.126,60.014 pad.2@19.126,61.614 pad.2@19.126,66.894 pad.2@19.126,68.494 pad.2@19.126,70.144 pad.2@19.126,71.744 pad.2@19.126,73.297 pad.2@19.126,74.897 pad.2@19.126,86.847 pad.2@19.126,88.447 pad.2@19.126,90.097 pad.2@19.126,91.697 pad.2@19.126,93.25 pad.2@19.126,94.85 pad.2@19.126,100.242 pad.2@19.126,101.842 pad.2@19.126,103.492 pad.2@19.126,105.092 pad.2@19.126,106.644 pad.2@19.126,108.244 pad.2@19.639,54.409 pad.2@19.639,56.059 pad.2@19.639,57.659 pad.2@19.639,59.212 pad.2@19.639,60.812 pad.2@19.639,67.693 pad.2@19.639,69.343 pad.2@19.639,70.943 pad.2@19.639,72.496 pad.2@19.639,74.096 pad.2@19.639,87.646 pad.2@19.639,89.296 pad.2@19.639,90.896 pad.2@19.639,92.448 pad.2@19.639,94.048 pad.2@19.639,101.04 pad.2@19.639,102.69 pad.2@19.639,104.29 pad.2@19.639,105.843 pad.2@19.639,107.443 pad.2@20.126,53.611 pad.2@20.126,55.211 pad.2@20.126,56.861 pad.2@20.126,58.461 pad.2@20.126,60.014 pad.2@20.126,61.614 pad.2@20.126,66.894 pad.2@20.126,68.494 pad.2@20.126,70.144 pad.2@20.126,71.744 pad.2@20.126,73.297 pad.2@20.126,74.897 pad.2@20.126,86.847 pad.2@20.126,88.447 pad.2@20.126,90.097 pad.2@20.126,91.697 pad.2@20.126,93.25 pad.2@20.126,94.85 pad.2@20.126,100.242 pad.2@20.126,101.842 pad.2@20.126,103.492 pad.2@20.126,105.092 pad.2@20.126,106.644 pad.2@20.126,108.244 pad.2@20.626,54.409 pad.2@20.626,56.059 pad.2@20.626,57.659 pad.2@20.626,59.212 pad.2@20.626,60.812 pad.2@20.626,67.693 pad.2@20.626,69.343 pad.2@20.626,70.943 pad.2@20.626,72.496 pad.2@20.626,74.096 pad.2@20.626,87.646 pad.2@20.626,89.296 pad.2@20.626,90.896 pad.2@20.626,92.448 pad.2@20.626,94.048 pad.2@20.626,101.04 pad.2@20.626,102.69 pad.2@20.626,104.29 pad.2@20.626,105.843 pad.2@20.626,107.443 pad.2@21.126,53.616 pad.2@21.126,55.216 pad.2@21.126,56.866 pad.2@21.126,58.466 pad.2@21.126,60.019 pad.2@21.126,61.619 pad.2@21.126,66.9 pad.2@21.126,68.5 pad.2@21.126,70.15 pad.2@21.126,71.75 pad.2@21.126,73.303 pad.2@21.126,74.903 pad.2@21.126,86.853 pad.2@21.126,88.453 pad.2@21.126,90.103 pad.2@21.126,91.703 pad.2@21.126,93.256 pad.2@21.126,94.855 pad.2@21.126,100.247 pad.2@21.126,101.847 pad.2@21.126,103.497 pad.2@21.126,105.097 pad.2@21.126,106.65 pad.2@21.126,108.25 pad.2@21.626,54.404 pad.2@21.626,56.054 pad.2@21.626,57.654 pad.2@21.626,59.207 pad.2@21.626,60.807 pad.2@21.626,67.687 pad.2@21.626,69.337 pad.2@21.626,70.937 pad.2@21.626,72.49 pad.2@21.626,74.09 pad.2@21.626,87.64 pad.2@21.626,89.29 pad.2@21.626,90.89 pad.2@21.626,92.443 pad.2@21.626,94.043 pad.2@21.626,101.035 pad.2@21.626,102.685 pad.2@21.626,104.285 pad.2@21.626,105.837 pad.2@21.626,107.437 pad.2@22.126,53.611 pad.2@22.126,55.211 pad.2@22.126,56.861 pad.2@22.126,58.461 pad.2@22.126,60.014 pad.2@22.126,61.614 pad.2@22.126,66.894 pad.2@22.126,68.494 pad.2@22.126,70.144 pad.2@22.126,71.744 pad.2@22.126,73.297 pad.2@22.126,74.897 pad.2@22.126,86.847 pad.2@22.126,88.447 pad.2@22.126,90.097 pad.2@22.126,91.697 pad.2@22.126,93.25 pad.2@22.126,94.85 pad.2@22.126,100.242 pad.2@22.126,101.842 pad.2@22.126,103.492 pad.2@22.126,105.092 pad.2@22.126,106.644 pad.2@22.126,108.244 pad.2@22.626,54.409 pad.2@22.626,56.059 pad.2@22.626,57.659 pad.2@22.626,59.212 pad.2@22.626,60.812 pad.2@22.626,67.693 pad.2@22.626,69.343 pad.2@22.626,70.943 pad.2@22.626,72.496 pad.2@22.626,74.096 pad.2@22.626,87.646 pad.2@22.626,89.296 pad.2@22.626,90.896 pad.2@22.626,92.448 pad.2@22.626,94.048 pad.2@22.626,101.04 pad.2@22.626,102.69 pad.2@22.626,104.29 pad.2@22.626,105.843 pad.2@22.626,107.443 pad.2@23.126,53.616 pad.2@23.126,55.216 pad.2@23.126,56.866 pad.2@23.126,58.466 pad.2@23.126,60.019 pad.2@23.126,61.619 pad.2@23.126,66.9 pad.2@23.126,68.5 pad.2@23.126,70.15 pad.2@23.126,71.75 pad.2@23.126,73.303 pad.2@23.126,74.903 pad.2@23.126,86.853 pad.2@23.126,88.453 pad.2@23.126,90.103 pad.2@23.126,91.703 pad.2@23.126,93.256 pad.2@23.126,94.855 pad.2@23.126,100.247 pad.2@23.126,101.847 pad.2@23.126,103.497 pad.2@23.126,105.097 pad.2@23.126,106.65 pad.2@23.126,108.25 pad.2@23.626,54.404 pad.2@23.626,56.054 pad.2@23.626,57.654 pad.2@23.626,59.207 pad.2@23.626,60.807 pad.2@23.626,67.687 pad.2@23.626,69.337 pad.2@23.626,70.937 pad.2@23.626,72.49 pad.2@23.626,74.09 pad.2@23.626,87.64 pad.2@23.626,89.29 pad.2@23.626,90.89 pad.2@23.626,92.443 pad.2@23.626,94.043 pad.2@23.626,101.035 pad.2@23.626,102.685 pad.2@23.626,104.285 pad.2@23.626,105.837 pad.2@23.626,107.437 pad.2@24.126,53.611 pad.2@24.126,55.211 pad.2@24.126,56.861 pad.2@24.126,58.461 pad.2@24.126,60.014 pad.2@24.126,61.614 pad.2@24.126,66.894 pad.2@24.126,68.494 pad.2@24.126,70.144 pad.2@24.126,71.744 pad.2@24.126,73.297 pad.2@24.126,74.897 pad.2@24.126,86.847 pad.2@24.126,88.447 pad.2@24.126,90.097 pad.2@24.126,91.697 pad.2@24.126,93.25 pad.2@24.126,94.85 pad.2@24.126,100.242 pad.2@24.126,101.842 pad.2@24.126,103.492 pad.2@24.126,105.092 pad.2@24.126,106.644 pad.2@24.126,108.244 pad.2@24.626,54.409 pad.2@24.626,56.059 pad.2@24.626,57.659 pad.2@24.626,59.212 pad.2@24.626,60.812 pad.2@24.626,67.693 pad.2@24.626,69.343 pad.2@24.626,70.943 pad.2@24.626,72.496 pad.2@24.626,74.096 pad.2@24.626,87.646 pad.2@24.626,89.296 pad.2@24.626,90.896 pad.2@24.626,92.448 pad.2@24.626,94.048 pad.2@24.626,101.04 pad.2@24.626,102.69 pad.2@24.626,104.29 pad.2@24.626,105.843 pad.2@24.626,107.443 pad.2@25.126,53.616 pad.2@25.126,55.216 pad.2@25.126,56.866 pad.2@25.126,58.466 pad.2@25.126,60.019 pad.2@25.126,61.619 pad.2@25.126,66.9 pad.2@25.126,68.5 pad.2@25.126,70.15 pad.2@25.126,71.75 pad.2@25.126,73.303 pad.2@25.126,74.903 pad.2@25.126,86.853 pad.2@25.126,88.453 pad.2@25.126,90.103 pad.2@25.126,91.703 pad.2@25.126,93.256 pad.2@25.126,94.855 pad.2@25.126,100.247 pad.2@25.126,101.847 pad.2@25.126,103.497 pad.2@25.126,105.097 pad.2@25.126,106.65 pad.2@25.126,108.25 pad.2@25.626,54.409 pad.2@25.626,56.059 pad.2@25.626,57.659 pad.2@25.626,59.212 pad.2@25.626,60.812 pad.2@25.626,67.693 pad.2@25.626,69.343 pad.2@25.626,70.943 pad.2@25.626,72.496 pad.2@25.626,74.096 pad.2@25.626,87.646 pad.2@25.626,89.296 pad.2@25.626,90.896 pad.2@25.626,92.448 pad.2@25.626,94.048 pad.2@25.626,101.04 pad.2@25.626,102.69 pad.2@25.626,104.29 pad.2@25.626,105.843 pad.2@25.626,107.443 pad.2@26.126,53.616 pad.2@26.126,55.216 pad.2@26.126,56.866 pad.2@26.126,58.466 pad.2@26.126,60.019 pad.2@26.126,61.619 pad.2@26.126,66.9 pad.2@26.126,68.5 pad.2@26.126,70.15 pad.2@26.126,71.75 pad.2@26.126,73.303 pad.2@26.126,74.903 pad.2@26.126,86.853 pad.2@26.126,88.453 pad.2@26.126,90.103 pad.2@26.126,91.703 pad.2@26.126,93.256 pad.2@26.126,94.855 pad.2@26.126,100.247 pad.2@26.126,101.847 pad.2@26.126,103.497 pad.2@26.126,105.097 pad.2@26.126,106.65 pad.2@26.126,108.25 Q1_P3.2-3-4-5-6-7-8 Q2_P3.2-3-4-5-6-7-8 Q3_P3.2-3-4-5-6-7-8 Q4_P3.2-3-4-5-6-7-8 Q5_P3.9 Q6_P3.9 Q7_P3.9 Q8_P3.9 R5_P3.1 R6_P3.1 R7_P3.1 R8_P3.1 U1_P3.4 | length 25.1
  Top Layer w0.6: 15.376,54.572 pad.2@17.126,54.572 17.626,54.572 ; 15.626,88 15.634,88.008 pad.2@17.126,88.008 17.626,88.008 ; 15.626,101.178 15.651,101.203 pad.2@17.126,101.203 17.626,101.203 ; 15.634,67.855 pad.2@17.126,67.855 17.626,67.855 ; R5_P3.1@17.876,50.975 17.876,52.25 17.626,52.5 17.626,54.572 ; R6_P3.1@17.876,64.258 17.876,65.805 17.626,66.055 17.626,67.855 ; R7_P3.1@17.876,84.411 17.876,85.75 17.626,86 17.626,88.008 ; R8_P3.1@17.876,97.606 17.876,99 17.626,99.25 17.626,101.203 ; pad.2@18.126,54.572 17.626,54.572 ; pad.2@18.126,67.855 17.626,67.855 ; pad.2@18.126,88.008 17.626,88.008 ; pad.2@18.126,101.203 17.626,101.203
  other v1: 30.645,111.348 31.881,111.348 29.645,112.074 32.881,112.074 29.263,113.25 33.263,113.25 29.263,114.583 33.263,114.583 29.263,115.917 33.263,115.917 29.263,117.25 33.263,117.25 29.645,118.426 32.881,118.426 30.645,119.152 31.881,119.152
G_HS_P1: J5_P1.2 R1_P1.1 R2_P1.1 R3_P1.1 R4_P1.1 | length 46.6
  Top Layer w0.75: R1_P1.1@93.376,50.975 R2_P1.1@93.376,64.258 J5_P1.2@93.376,81.199 R3_P1.1@93.376,84.411 R4_P1.1@93.376,97.606
G_HS_P2: J5_P2.2 R1_P2.1 R2_P2.1 R3_P2.1 R4_P2.1 | length 46.6
  Top Layer w0.75: R1_P2.1@53.376,50.975 R2_P2.1@53.376,64.258 J5_P2.2@53.376,81.199 R3_P2.1@53.376,84.411 R4_P2.1@53.376,97.606
G_HS_P3: J5_P3.2 R1_P3.1 R2_P3.1 R3_P3.1 R4_P3.1 | length 46.6
  Top Layer w0.75: R1_P3.1@13.376,50.975 R2_P3.1@13.376,64.258 J5_P3.2@13.376,81.199 R3_P3.1@13.376,84.411 R4_P3.1@13.376,97.606
G_LS_P1: J6_P1.2 R9_P1.1 R10_P1.1 R11_P1.1 R12_P1.1 | length 46.6
  Top Layer w0.75: R9_P1.1@108.126,50.975 R10_P1.1@108.126,64.258 R11_P1.1@108.126,84.411 R12_P1.1@108.126,97.606
G_LS_P2: J6_P2.2 R9_P2.1 R10_P2.1 R11_P2.1 R12_P2.1 | length 46.6
  Top Layer w0.75: R9_P2.1@68.126,50.975 R10_P2.1@68.126,64.258 R11_P2.1@68.126,84.411 R12_P2.1@68.126,97.606
G_LS_P3: J6_P3.2 R9_P3.1 R10_P3.1 R11_P3.1 R12_P3.1 | length 46.6
  Top Layer w0.75: R9_P3.1@28.126,50.975 R10_P3.1@28.126,64.258 R11_P3.1@28.126,84.411 R12_P3.1@28.126,97.606
GND_P1: J2_P1.2 | length 6.6
  Top Layer w0.6: J2_P1.2@82.54,120.25 89.092,120.25
GND_P2: J2_P2.2 | length 6.6
  Top Layer w0.6: J2_P2.2@42.54,120.25 49.092,120.25
GND_P3: J2_P3.2 | length 6.6
  Top Layer w0.6: J2_P3.2@2.54,120.25 9.092,120.25
IOUT_P1: C4_P1.2 J2_P1.3 R17_P1.1 | length 6.2
  Top Layer w0.25: R17_P1.1@84.92,112.886 84.945,112.886 85.72,113.661 85.72,114.053 86.495,114.828 86.495,117.2 85.985,117.71 J2_P1.3@85.46,117.71
IOUT_P2: C4_P2.2 J2_P2.3 R17_P2.1 | length 6.2
  Top Layer w0.25: 44.92,112.886 44.945,112.886 45.72,113.661 45.72,114.053 46.495,114.828 46.495,117.2 45.985,117.71 J2_P2.3@45.46,117.71
IOUT_P3: C4_P3.2 J2_P3.3 R17_P3.1 | length 6.2
  Top Layer w0.25: R17_P3.1@4.92,112.886 4.945,112.886 5.72,113.661 5.72,114.053 6.495,114.828 6.495,117.2 5.985,117.71 J2_P3.3@5.46,117.71
NetC3_P1_2: C3_P1.2 C4_P1.1 pad.2@81.175,121.183 pad.2@81.675,119.33 pad.2@82.75,119.33 pad.2@82.175,121.186 pad.2@82.955,114.858 pad.2@83.25,121.186 pad.2@83.75,119.33 pad.2@83.955,114.858 pad.2@87.5,127.3 pad.2@88.55,127.3 U1_P1.2 | length 3.8
  Top Layer w0.6: pad.2@82.955,114.858 C4_P1.1@84.972,114.858 ; C3_P1.2@86.75,127.3 pad.2@87.5,127.3 88,127.3 pad.2@88.55,127.3
NetC3_P2_2: C3_P2.2 C4_P2.1 pad.2@41.175,121.183 pad.2@41.675,119.33 pad.2@42.75,119.33 pad.2@42.175,121.186 pad.2@42.955,114.858 pad.2@43.25,121.186 pad.2@43.75,119.33 pad.2@43.955,114.858 pad.2@47.5,127.3 pad.2@48.55,127.3 U1_P2.2 | length 3.8
  Top Layer w0.6: pad.2@42.955,114.858 44.972,114.858 ; C3_P2.2@46.75,127.3 pad.2@47.5,127.3 48,127.3 pad.2@48.55,127.3
NetC3_P3_2: C3_P3.2 C4_P3.1 pad.2@1.175,121.183 pad.2@1.675,119.33 pad.2@2.75,119.33 pad.2@2.175,121.186 pad.2@2.955,114.858 pad.2@3.25,121.186 pad.2@3.75,119.33 pad.2@3.955,114.858 pad.2@7.5,127.3 pad.2@8.55,127.3 U1_P3.2 | length 3.8
  Top Layer w0.6: pad.2@2.955,114.858 C4_P3.1@4.972,114.858 ; C3_P3.2@6.75,127.3 pad.2@7.5,127.3 8,127.3 pad.2@8.55,127.3
NetJ1_P1_1: J1_P1.1 U1_P1.5
  other v1: 110.691,121.348 111.928,121.348 109.692,122.074 112.927,122.074 109.309,123.25 113.309,123.25 109.309,124.583 113.309,124.583 109.309,125.917 113.309,125.917 109.309,127.25 113.309,127.25 109.692,128.426 112.927,128.426 110.691,129.152 111.928,129.152
NetJ1_P2_1: J1_P2.1 U1_P2.5
  other v1: 70.649,121.348 71.885,121.348 69.649,122.074 72.885,122.074 69.267,123.25 73.267,123.25 69.267,124.583 73.267,124.583 69.267,125.917 73.267,125.917 69.267,127.25 73.267,127.25 69.649,128.426 72.885,128.426 70.649,129.152 71.885,129.152
NetJ1_P3_1: J1_P3.1 U1_P3.5
  other v1: 30.645,121.348 31.881,121.348 29.645,122.074 32.881,122.074 29.263,123.25 33.263,123.25 29.263,124.583 33.263,124.583 29.263,125.917 33.263,125.917 29.263,127.25 33.263,127.25 29.645,128.426 32.881,128.426 30.645,129.152 31.881,129.152
NetQ1_P1_1: Q1_P1.1 R1_P1.2 R5_P1.2 | length 4.6
  Top Layer w0.6: R1_P1.2@94.876,50.975 R5_P1.2@96.376,50.975
  Top Layer w0.75: R1_P1.2@94.876,50.975 94.876,53.347 94.901,53.372 Q1_P1.1@95.626,53.372
NetQ1_P2_1: Q1_P2.1 R1_P2.2 R5_P2.2 | length 4.6
  Top Layer w0.6: R1_P2.2@54.876,50.975 R5_P2.2@56.376,50.975
  Top Layer w0.75: R1_P2.2@54.876,50.975 54.876,53.347 54.901,53.372 Q1_P2.1@55.626,53.372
